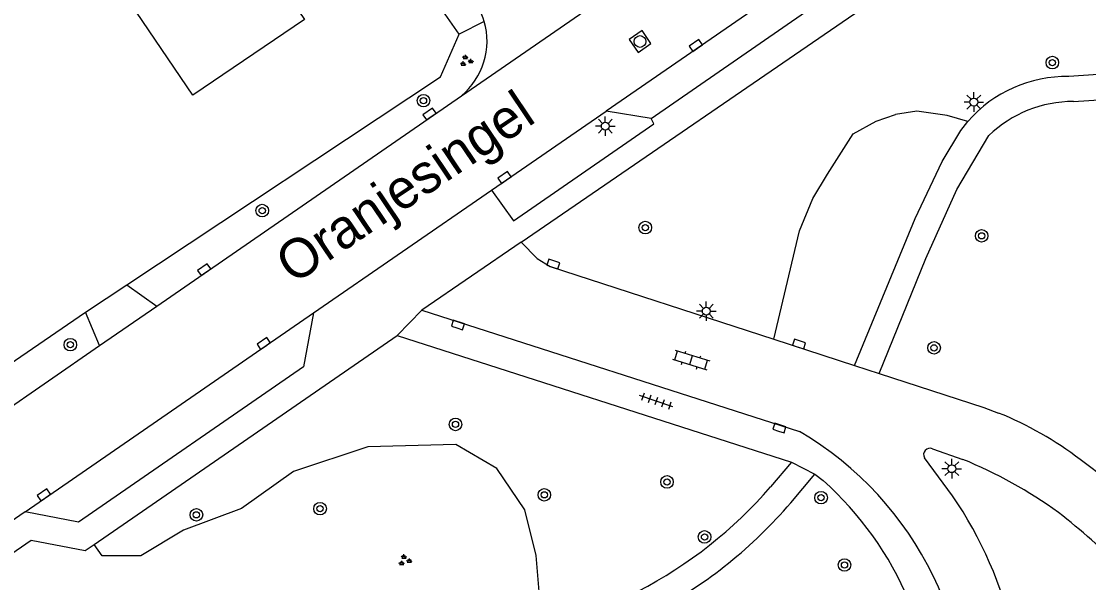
# Model space of a CAD drawing. Extents: x 137999 to 141000, y 397500 to 400501.
# Drawn here: x 138040.8 to 138108.9, y 399667.3 to 399703.1 of the extents above; entities that cross this region are included whole.
import ezdxf

# ---------------------------------------------------------------- set-up
doc = ezdxf.new("R2010")
doc.units = 0
for name, color, linetype in [('gg-afsc-erfafscheiding', 7, 'Continuous'), ('gg-anno-openbare ruimte label', 7, 'Continuous'), ('gg-bbg-gedigitaliseerde bebouwing', 7, 'Continuous'), ('gg-bbg-hoofdgebouw', 7, 'Continuous'), ('gg-knt-verharding', 7, 'Continuous'), ('gg-knt-verharding nz', 7, 'Continuous'), ('gt-grn-groengrens', 7, 'Continuous'), ('gt-grn-weggrens', 7, 'Continuous'), ('gt-symb-boom', 7, 'Continuous'), ('gt-symb-groenvak', 7, 'Continuous'), ('gt-symb-klinker verharding', 7, 'Continuous'), ('gt-symb-kolk', 7, 'Continuous'), ('gt-symb-lichtmast', 7, 'Continuous'), ('gt-symb-rioolschacht', 7, 'Continuous'), ('gt-symb-tegel verharding', 7, 'Continuous')]:
    doc.layers.add(name, color=color, linetype=linetype)

# ---------------------------------------------------------------- blocks, each defined once
blk = doc.blocks.new('gt0-BOOM')
at = {"layer": 'gt-symb-boom'}
for radius in [0.4, 0.2]:
    blk.add_circle((0, 0), radius, dxfattribs=at)
blk = doc.blocks.new('gt0-KOLK')
at = {"layer": 'gt-symb-kolk'}
blk.add_lwpolyline([(0, 0), (0.375, 0), (0.375, 0.4), (-0.375, 0.4), (-0.375, 0), (0, 0)], dxfattribs=at)
blk = doc.blocks.new('gt0-TEG1')
at = {"layer": 'gt-symb-tegel verharding'}
for p, q in [((-1.125, 0), (1.125, 0)), ((-0.9, -0.25), (-0.9, 0.25)), ((-0.45, -0.25), (-0.45, 0.25)), ((0, -0.25), (0, 0.25)), ((0.45, -0.25), (0.45, 0.25)), ((0.9, -0.25), (0.9, 0.25))]:
    blk.add_line(p, q, dxfattribs=at)
blk = doc.blocks.new('gt0-KL1')
at = {"layer": 'gt-symb-klinker verharding'}
for p, q in [((-1.15, 0.3), (1.15, 0.3)), ((-1, -0.3), (-1, 0.3)), ((-0.5, 0.3), (-0.5, 0.45)), ((0, -0.3), (0, 0.3)), ((0.5, 0.3), (0.5, 0.45)), ((1, -0.3), (1, 0.3)), ((-1.15, -0.3), (1.15, -0.3)), ((-0.5, -0.45), (-0.5, -0.3)), ((0.5, -0.45), (0.5, -0.3))]:
    blk.add_line(p, q, dxfattribs=at)
blk = doc.blocks.new('gt0-LMAST')
at = {"layer": 'gt-symb-lichtmast'}
for p, q in [((-0.182, 0.173), (-0.447, 0.438)), ((-0.005, 0.246), (-0.005, 0.621)), ((0.172, 0.173), (0.437, 0.438)), ((-0.255, -0.004), (-0.63, -0.004)), ((-0.182, -0.181), (-0.447, -0.446)), ((-0.005, -0.254), (-0.005, -0.629)), ((0.437, -0.446), (0.172, -0.181)), ((0.245, -0.004), (0.62, -0.004))]:
    blk.add_line(p, q, dxfattribs=at)
blk.add_circle((-0.005, -0.004), 0.25, dxfattribs=at)
blk = doc.blocks.new('gt0-GRVAK')
at = {"layer": 'gt-symb-groenvak'}
for p, q in [((-0.11, 0.189), (-0.228, 0.24)), ((-0.182, 0.153), (0.088, 0.153)), ((-0.091, 0.211), (-0.156, 0.322)), ((-0.047, 0.214), (-0.047, 0.393)), ((-0.004, 0.211), (0.061, 0.322)), ((0.015, 0.189), (0.133, 0.24)), ((0.262, -0.052), (0.197, 0.059)), ((0.305, -0.049), (0.305, 0.13)), ((0.349, -0.052), (0.414, 0.059)), ((-0.245, -0.228), (-0.363, -0.177)), ((-0.318, -0.264), (-0.047, -0.264)), ((-0.226, -0.206), (-0.291, -0.095)), ((-0.183, -0.203), (-0.183, -0.024)), ((-0.139, -0.206), (-0.074, -0.095)), ((-0.12, -0.228), (-0.002, -0.177)), ((0.243, -0.074), (0.125, -0.023)), ((0.17, -0.11), (0.441, -0.11)), ((0.368, -0.074), (0.486, -0.023))]:
    blk.add_line(p, q, dxfattribs=at)
blk = doc.blocks.new('gt0-RS')
at = {"layer": 'gt-symb-rioolschacht'}
blk.add_lwpolyline([(-0.5, -0.5), (0.5, -0.5), (0.5, 0.5), (-0.5, 0.5)], close=True, dxfattribs=at)
blk.add_circle((0, 0), 0.375, dxfattribs=at)

msp = doc.modelspace()

# ---------------------------------------------------------------- linework, layer by layer
at = {"layer": 'gg-afsc-erfafscheiding'}
for p, q in [((138068.728, 399702.317), (138062.518, 399711.323)), ((138026.626, 399672.088), (138044.909, 399684.587))]:
    msp.add_line(p, q, dxfattribs=at)
msp.add_lwpolyline([(138047.539, 399686.339), (138067.541, 399699.61), (138068.728, 399702.317)], dxfattribs=at)
at = {"layer": 'gg-bbg-gedigitaliseerde bebouwing'}
msp.add_lwpolyline([(138051.74, 399698.44), (138047.339, 399704.947), (138047.613, 399705.133), (138044.481, 399709.745), (138043.196, 399708.872), (138041.162, 399711.866), (138047.57, 399716.19)], dxfattribs=at)
at = {"layer": 'gg-bbg-hoofdgebouw'}
msp.add_lwpolyline([(138047.57, 399716.19), (138049.4, 399713.47), (138051.14, 399714.64), (138058.87, 399703.26), (138051.74, 399698.44)], dxfattribs=at)
at = {"layer": 'gg-knt-verharding'}
for p, q in [((138072.681, 399689.055), (138125.61, 399725.35)), ((138118.79, 399700.354), (138107.62, 399699.62)), ((138049.453, 399684.961), (138068.878, 399698.394)), ((138070.789, 399692.364), (138078.116, 399697.417)), ((138080.98, 399696.94), (138078.116, 399697.417)), ((138059.438, 399684.535), (138070.789, 399692.364)), ((138072.681, 399689.055), (138066.36, 399684.72)), ((138044.909, 399684.587), (138047.539, 399686.339)), ((138047.539, 399686.339), (138049.453, 399684.961)), ((138066.36, 399684.72), (138090.435, 399676.978)), ((138045.792, 399682.455), (138044.909, 399684.587)), ((138045.46, 399669.77), (138064.77, 399683.09)), ((138064.77, 399683.09), (138089.92, 399675.01)), ((138088.812, 399682.86), (138093.943, 399681.189)), ((138027.817, 399670.026), (138045.792, 399682.455)), ((138093.943, 399681.189), (138095.531, 399680.672)), ((138098.93, 399675.87), (138100.849, 399675.196)), ((138100.2, 399672.87), (138098.41, 399675.29)), ((138089.92, 399675.01), (138088.599, 399673.439)), ((138089.879, 399672.419), (138091.42, 399674.24)), ((138091.42, 399674.24), (138091.95, 399673.84))]:
    msp.add_line(p, q, dxfattribs=at)
for points in [[(138080.98, 399696.94), (138139.487, 399737.403), (138139.974, 399740.081)], [(138107.919, 399698.03), (138119.3, 399698.77), (138120.929, 399696.252)], [(138070.789, 399692.364), (138072.19, 399690.41), (138081.14, 399696.61), (138080.98, 399696.94)], [(138093.943, 399681.189), (138097.81, 399690.57), (138099.54, 399694.19), (138100.721, 399696.181), (138101.181, 399696.761)], [(138095.531, 399680.672), (138098.49, 399688.01), (138100.47, 399692.42), (138102.52, 399695.85)], [(138072.681, 399689.055), (138073.71, 399688), (138074.53, 399687.51), (138088.812, 399682.86)], [(138059.438, 399684.535), (138058.813, 399681.098), (138044.457, 399671.184), (138041.053, 399671.855)], [(138095.531, 399680.672), (138102.2, 399678.5), (138103.136, 399678.152)], [(138041.053, 399671.855), (138009.737, 399650.257), (138009.16, 399649.874)], [(138038.28, 399667.866), (138041.43, 399670.04), (138044.88, 399669.37), (138045.46, 399669.77)]]:
    msp.add_lwpolyline(points, dxfattribs=at)
for centre, radius, start, end in [((138065.992, 399701.879), 4.519, 16.21106, 38.19752), ((138065.986, 399701.876), 4.527, 309.71516, 16.22533), ((138107.459, 399691.303), 8.318, 88.88792, 138.99577), ((138107.917, 399690.26), 7.77, 89.98361, 133.99199), ((138094.698, 399657.335), 22.462, 52.58562, 67.93409), ((138079.446, 399658.257), 21.708, 352.33119, 59.58827), ((138098.763, 399675.496), 0.409, 65.9376, 210.30666), ((138089.388, 399647.252), 30.203, 54.41015, 67.70038), ((138076.862, 399632.412), 53.103, 44.46947, 53.63988), ((138077.704, 399657.888), 21.387, 22.77997, 48.23319), ((138066.947, 399692.24), 28.675, 297.43702, 319.03139), ((138066.955, 399692.1), 30.213, 298.38841, 319.35283), ((138078.651, 399658.152), 26.096, 351.51952, 34.33219), ((138058.182, 399611.314), 77.717, 47.07574, 51.11866)]:
    msp.add_arc(centre, radius, start, end, dxfattribs=at)
at = {"layer": 'gg-knt-verharding nz'}
for p, q in [((138103.483, 399714.913), (138078.116, 399697.417)), ((138045.792, 399682.455), (138049.453, 399684.961)), ((138041.053, 399671.855), (138059.438, 399684.535))]:
    msp.add_line(p, q, dxfattribs=at)
at = {"layer": 'gt-grn-groengrens'}
msp.add_line((138070.332, 399703.141), (138068.728, 399702.317), dxfattribs=at)
for points in [[(138088.812, 399682.86), (138090.431, 399689.768), (138091.282, 399691.829), (138092.223, 399693.384), (138093.857, 399695.963), (138095.325, 399696.767), (138096.569, 399697.206)], [(138101.181, 399696.761), (138099.857, 399697.139), (138097.927, 399697.41), (138096.569, 399697.206)], [(138074.479, 399664.624), (138073.881, 399666.264), (138073.653, 399669.068), (138072.919, 399671.966), (138071.135, 399674.621), (138068.521, 399676.147), (138062.909, 399675.999), (138058.177, 399674.412), (138054.844, 399672.063), (138051.143, 399670.677), (138048.441, 399669.041), (138045.97, 399669.03), (138045.46, 399669.77)]]:
    msp.add_lwpolyline(points, dxfattribs=at)
at = {"layer": 'gt-grn-weggrens'}
for p, q in [((138068.878, 399698.394), (138079.545, 399705.744)), ((138066.36, 399684.72), (138064.77, 399683.09)), ((138089.92, 399675.01), (138091.42, 399674.24))]:
    msp.add_line(p, q, dxfattribs=at)

# ---------------------------------------------------------------- block references
at = {"layer": 'gt-symb-boom'}
for p in [(138106.568, 399700.509), (138066.457, 399698.08), (138056.174, 399691.068), (138080.602, 399689.983), (138102.057, 399689.456), (138043.936, 399682.51), (138099.023, 399682.307), (138068.501, 399677.425), (138081.99, 399673.755), (138074.163, 399672.93), (138091.817, 399672.747), (138059.863, 399672.045), (138051.977, 399671.656), (138084.385, 399670.247), (138093.312, 399668.457)]:
    msp.add_blockref('gt0-BOOM', p, dxfattribs=at)
at = {"layer": 'gt-symb-groenvak'}
for p in [(138069.175, 399700.617), (138065.257, 399668.747)]:
    msp.add_blockref('gt0-GRVAK', p, dxfattribs=at)
at = {"layer": 'gt-symb-klinker verharding', "rotation": -17.165946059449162}
msp.add_blockref('gt0-KL1', (138083.527, 399681.527), dxfattribs=at)
at = {"layer": 'gt-symb-kolk'}
for p, rotation in [((138083.942, 399701.435), 34.6589362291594), ((138066.952, 399697.063), 34.6589362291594), ((138071.736, 399693.016), 34.6589362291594), ((138052.584, 399687.131), 34.6589362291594), ((138074.677, 399687.462), -18.054552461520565), ((138068.594, 399683.577), -18.054552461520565), ((138056.377, 399682.427), 34.6589362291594), ((138090.352, 399682.357), -18.054552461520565), ((138089.097, 399677), -18.00007459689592), ((138042.366, 399672.763), 34.65893622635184)]:
    msp.add_blockref('gt0-KOLK', p, dxfattribs=dict(at, rotation=rotation))
at = {"layer": 'gt-symb-lichtmast'}
for p in [(138101.563, 399697.993), (138078.058, 399696.458), (138084.499, 399684.654), (138100.158, 399674.601)]:
    msp.add_blockref('gt0-LMAST', p, dxfattribs=at)
at = {"layer": 'gt-symb-rioolschacht', "rotation": 34.6589362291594}
msp.add_blockref('gt0-RS', (138080.27, 399701.855), dxfattribs=at)
at = {"layer": 'gt-symb-tegel verharding', "rotation": 161.45633066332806}
msp.add_blockref('gt0-TEG1', (138081.302, 399678.901), dxfattribs=at)

# ---------------------------------------------------------------- texts
at = {"layer": 'gg-anno-openbare ruimte label'}
msp.add_text('Oranjesingel', height=2.5, rotation=33.9, dxfattribs=at).set_placement((138058.159, 399686.313))

doc.saveas('drawing.dxf')
